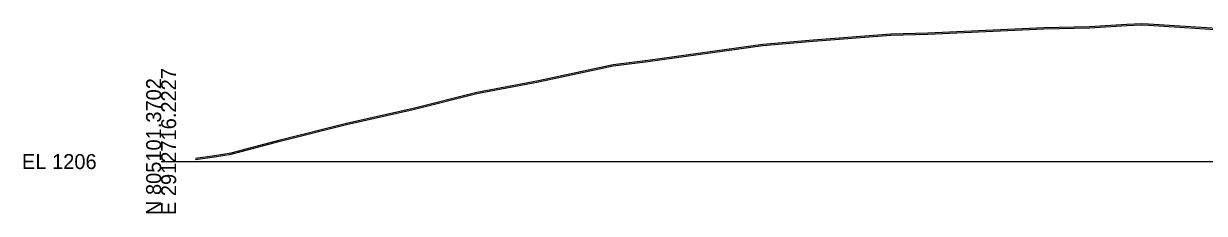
# Model space of a CAD drawing. Extents: x -231 to 794, y -10 to 23644.
# Drawn here: x -25.7 to 194.9, y 6990.3 to 7025.8 of the extents above; entities that cross this region are included whole.
import ezdxf

# ---------------------------------------------------------------- set-up
doc = ezdxf.new("R2010")
doc.units = 0
for name, color, linetype in [('DESIGN - SHEET - Light Grid', 7, 'Continuous'), ('SURVEY - GROUND - Bottom of Topsoil Layer', 7, 'Continuous'), ('SURVEY - GROUND - Top of Ground', 7, 'Continuous')]:
    doc.layers.add(name, color=color, linetype=linetype)

msp = doc.modelspace()

# ---------------------------------------------------------------- linework, layer by layer
at = {"layer": 'DESIGN - SHEET - Light Grid'}
msp.add_line((0, 7000), (300, 7000), dxfattribs=at)
at = {"layer": 'SURVEY - GROUND - Bottom of Topsoil Layer'}
for p, q in [((121.8, 7022.51), (136.33, 7023.66)), ((136.33, 7023.66), (143.25, 7023.85)), ((143.25, 7023.85), (155.46, 7024.41)), ((155.46, 7024.41), (164.92, 7024.8)), ((164.92, 7024.8), (173.44, 7024.98)), ((173.44, 7024.98), (180.43, 7025.47)), ((180.43, 7025.47), (183.24, 7025.55)), ((183.24, 7025.55), (184.43, 7025.51)), ((184.43, 7025.51), (200.24, 7024.48)), ((90.91, 7018.7), (112.42, 7021.73)), ((112.42, 7021.73), (121.8, 7022.51)), ((70.49, 7014.93), (84.44, 7017.91)), ((84.44, 7017.91), (90.91, 7018.7)), ((59, 7012.73), (70.49, 7014.93)), ((47.07, 7009.72), (59, 7012.73)), ((34.61, 7006.96), (47.07, 7009.72)), ((22.26, 7003.83), (34.61, 7006.96)), ((13.11, 7001.4), (22.26, 7003.83)), ((6.43, 7000.37), (9.95, 7000.86)), ((9.95, 7000.86), (13.11, 7001.4))]:
    msp.add_line(p, q, dxfattribs=at)
at = {"layer": 'SURVEY - GROUND - Top of Ground'}
msp.add_lwpolyline([(6.43, 7000.62), (9.95, 7001.11), (13.11, 7001.65), (22.26, 7004.08), (34.61, 7007.21), (47.07, 7009.97), (59, 7012.98), (70.49, 7015.18), (84.44, 7018.16), (90.91, 7018.95), (112.42, 7021.98), (121.8, 7022.76), (136.33, 7023.91), (143.25, 7024.1), (155.46, 7024.66), (164.92, 7025.05), (173.44, 7025.23), (180.43, 7025.72), (183.24, 7025.8), (184.43, 7025.76), (200.24, 7024.73)], dxfattribs=at)

# ---------------------------------------------------------------- texts
at = {"layer": 'DESIGN - SHEET - Light Grid'}
for s, p in [('E 2912716.2227', (2.8, 6990)), ('N 805101.3702', (0, 6990))]:
    msp.add_text(s, height=2.8, rotation=90, dxfattribs=at).set_placement(p)
msp.add_text('EL 1206', height=2.8, dxfattribs=at).set_placement((-26, 6998.6))

doc.saveas('drawing.dxf')
